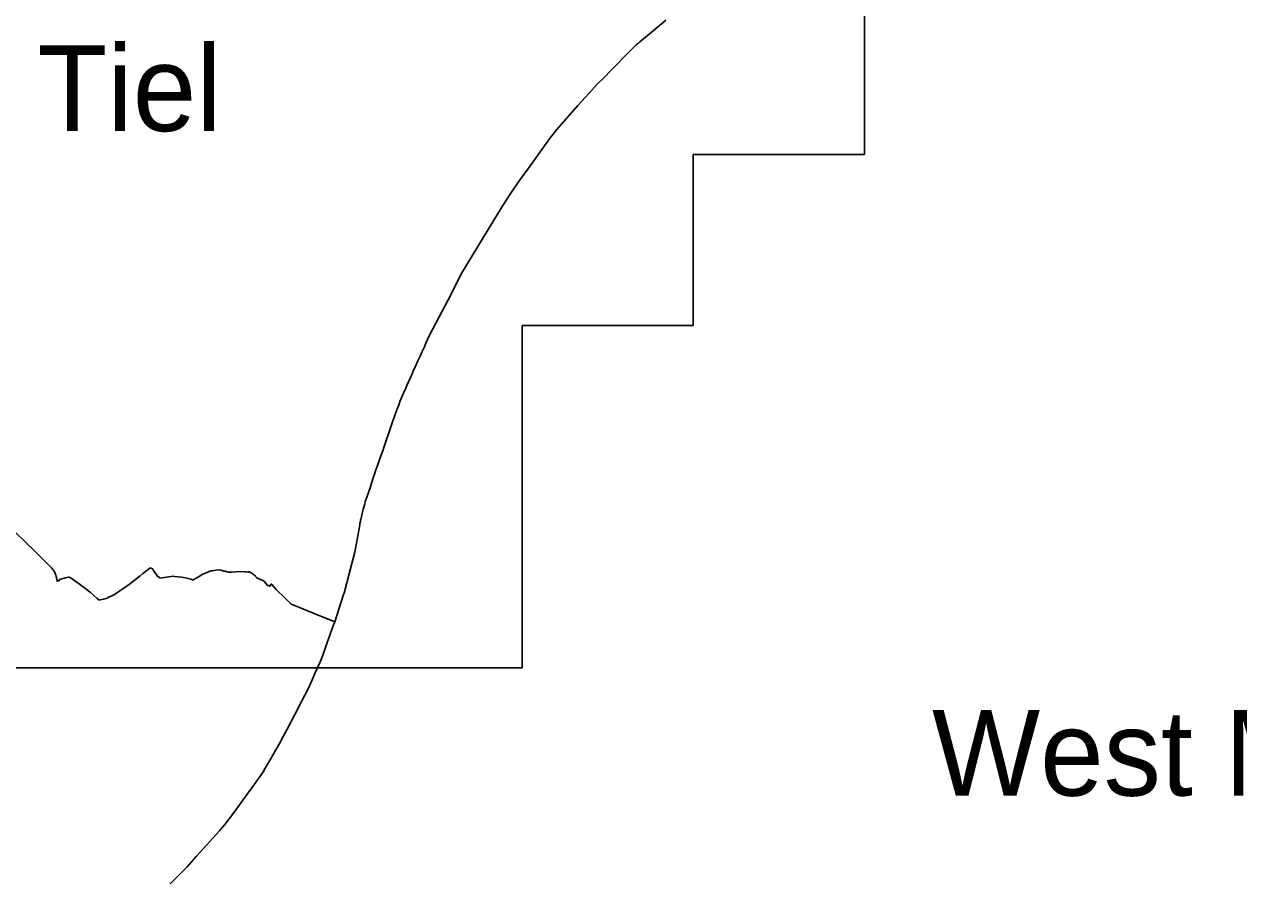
# Model space of a CAD drawing. Extents: x 113371 to 291721, y 393993 to 520143.
# Drawn here: x 155091 to 162187, y 427782 to 432755 of the extents above; entities that cross this region are included whole.
import ezdxf

# ---------------------------------------------------------------- set-up
doc = ezdxf.new("R2010")
doc.units = 0
for name, color, linetype in [('Boudingbox', 7, 'Continuous'), ('Default', 7, 'Continuous'), ('plaatsnamen', 7, 'Continuous'), ('vlieg gebied', 7, 'Continuous')]:
    doc.layers.add(name, color=color, linetype=linetype)

msp = doc.modelspace()

# ---------------------------------------------------------------- linework, layer by layer
at = {"layer": 'Boudingbox'}
for p, q in [((160000, 432995.215), (160000, 431995.215)), ((160000, 431995.215), (159000, 431995.215)), ((159000, 431995.215), (159000, 430995.215)), ((159000, 430995.215), (158000, 430995.215)), ((158000, 430995.215), (158000, 428995.215)), ((158000, 428995.215), (150000, 428995.215))]:
    msp.add_line(p, q, dxfattribs=at)
at = {"layer": 'Default'}
for points in [[(158840.615625, 432779.1125), (158777.135625, 432726.5825), (158720.495625, 432679.8225), (158688.725625, 432653.7425), (158679.835625, 432646.0125), (158669.255625, 432637.2825), (158658.075625, 432627.5925), (158644.595625, 432613.6525), (158602.395625, 432570.3625)], [(158602.395625, 432570.3625), (158644.595625, 432613.6525), (158658.075625, 432627.5925), (158669.255625, 432637.2825), (158679.835625, 432646.0125), (158688.725625, 432653.7425), (158720.495625, 432679.8225), (158777.135625, 432726.5825), (158840.615625, 432779.1125)], [(158602.395625, 432570.3625), (158551.075625, 432518.0425), (158515.545625, 432482.6625), (158480.465625, 432447.2025), (158439.405625, 432406.1125), (158390.795625, 432353.2825), (158344.145625, 432302.1425), (158325.745625, 432281.2925), (158244.325625, 432188.3925), (158240.585625, 432184.1225), (158203.205625, 432141.0825), (158164.965625, 432095.0525), (158114.925625, 432024.0425), (158071.385625, 431963.0225), (158036.605625, 431914.7325), (157989.405625, 431849.3225), (157948.955625, 431792.0025), (157930.655625, 431763.4525), (157887.545625, 431696.9025), (157856.185625, 431646.8425), (157647.905625, 431303.6125), (157566.495625, 431142.2825), (157513.785625, 431042.1125), (157457.465625, 430935.1025), (157438.405625, 430892.8725), (157428.825625, 430871.2225), (157416.765625, 430844.7025), (157404.285625, 430817.3225), (157391.425625, 430789.3325), (157377.655625, 430758.6825), (157364.215625, 430728.8825), (157357.545625, 430712.9125), (157347.615625, 430691.4325), (157336.865625, 430667.1625), (157327.405625, 430646.2725), (157320.235625, 430630.2625), (157308.905625, 430604.8925), (157305.375625, 430596.2825)], [(157305.375625, 430596.2825), (157308.905625, 430604.8925), (157320.235625, 430630.2625), (157327.405625, 430646.2725), (157336.865625, 430667.1625), (157347.615625, 430691.4325), (157357.545625, 430712.9125), (157364.215625, 430728.8825), (157377.655625, 430758.6825), (157391.425625, 430789.3325), (157404.285625, 430817.3225), (157416.765625, 430844.7025), (157428.825625, 430871.2225), (157438.405625, 430892.8725), (157457.465625, 430935.1025), (157513.785625, 431042.1125), (157566.495625, 431142.2825), (157647.905625, 431303.6125), (157856.185625, 431646.8425), (157887.545625, 431696.9025), (157930.655625, 431763.4525), (157948.955625, 431792.0025), (157989.405625, 431849.3225), (158036.605625, 431914.7325), (158071.385625, 431963.0225), (158114.925625, 432024.0425), (158164.965625, 432095.0525), (158203.205625, 432141.0825), (158240.585625, 432184.1225), (158244.325625, 432188.3925), (158325.745625, 432281.2925), (158344.145625, 432302.1425), (158390.795625, 432353.2825), (158439.405625, 432406.1125), (158480.465625, 432447.2025), (158515.545625, 432482.6625), (158551.075625, 432518.0425), (158602.395625, 432570.3625)], [(156784.805625, 429313.8825), (156905.645625, 429265.7325), (156956.895625, 429424.4425), (156959.555625, 429432.2025), (157005.475625, 429604.8225), (157022.755625, 429671.6825), (157051.655625, 429831.9825), (157052.535625, 429841.1825), (157053.465625, 429846.7025), (157055.055625, 429851.8625), (157056.625625, 429859.7625), (157059.225625, 429869.2725), (157061.695625, 429880.2125), (157072.155625, 429922.1725), (157074.095625, 429929.7325), (157080.355625, 429954.0125), (157083.855625, 429965.7025), (157111.675625, 430048.1325), (157128.605625, 430099.8925), (157137.745625, 430128.1425), (157142.255625, 430140.1425), (157152.885625, 430171.8225), (157164.585625, 430205.7225), (157174.715625, 430235.1225), (157185.555625, 430264.5125), (157191.935625, 430283.7325), (157201.525625, 430311.5225), (157205.265625, 430323.3825), (157218.825625, 430363.8925), (157230.305625, 430397.1825), (157236.095625, 430415.4925), (157244.085625, 430439.0025), (157247.575625, 430448.6825), (157268.435625, 430504.0325), (157276.915625, 430526.5625), (157287.845625, 430554.9325), (157293.215625, 430569.8125), (157305.375625, 430596.2825)], [(157305.375625, 430596.2825), (157293.215625, 430569.8125), (157287.845625, 430554.9325), (157276.915625, 430526.5625), (157268.435625, 430504.0325), (157247.575625, 430448.6825), (157244.085625, 430439.0025), (157236.095625, 430415.4925), (157230.305625, 430397.1825), (157218.825625, 430363.8925), (157205.265625, 430323.3825), (157201.525625, 430311.5225), (157191.935625, 430283.7325), (157185.555625, 430264.5125), (157174.715625, 430235.1225), (157164.585625, 430205.7225), (157152.885625, 430171.8225), (157142.255625, 430140.1425), (157137.745625, 430128.1425), (157128.605625, 430099.8925), (157111.675625, 430048.1325), (157083.855625, 429965.7025), (157080.355625, 429954.0125), (157074.095625, 429929.7325), (157072.155625, 429922.1725), (157061.695625, 429880.2125), (157059.225625, 429869.2725), (157056.625625, 429859.7625), (157055.055625, 429851.8625), (157053.465625, 429846.7025), (157052.535625, 429841.1825), (157051.655625, 429831.9825), (157022.755625, 429671.6825), (157005.475625, 429604.8225), (156959.555625, 429432.2025), (156956.895625, 429424.4425), (156905.645625, 429265.7325), (156898.295625, 429246.5025)], [(155357.905625, 429523.9125), (155352.895625, 429525.4725), (155348.495625, 429525.6425), (155332.525625, 429521.3325), (155303.785625, 429513.5325), (155297.835625, 429511.2225), (155295.425625, 429508.6225), (155295.225625, 429505.6225), (155283.335625, 429501.5225), (155281.665625, 429515.3325), (155278.315625, 429529.9025), (155276.185625, 429537.4825), (155274.045625, 429543.0225), (155272.455625, 429547.2225), (155270.085625, 429552.6025), (155267.595625, 429557.4025), (155261.815625, 429566.1325), (155257.955625, 429571.2025), (155250.265625, 429580.5325), (155240.885625, 429590.6125), (155145.715625, 429685.5625), (155106.945625, 429722.6625), (155025.835625, 429800.4525)], [(155025.835625, 429800.4525), (155106.945625, 429722.6625), (155145.715625, 429685.5625), (155240.885625, 429590.6125), (155250.265625, 429580.5325), (155257.955625, 429571.2025), (155261.815625, 429566.1325), (155267.595625, 429557.4025), (155270.085625, 429552.6025), (155272.455625, 429547.2225), (155274.045625, 429543.0225), (155276.185625, 429537.4825), (155278.315625, 429529.9025), (155281.665625, 429515.3325), (155283.335625, 429501.5225), (155295.225625, 429505.6225), (155295.425625, 429508.6225), (155297.835625, 429511.2225), (155303.785625, 429513.5325), (155332.525625, 429521.3325), (155348.495625, 429525.6425), (155352.895625, 429525.4725), (155357.905625, 429523.9125), (155361.525625, 429521.7425), (155365.135625, 429519.3625), (155405.725625, 429491.0625), (155420.395625, 429480.5725), (155461.605625, 429449.0825), (155476.085625, 429437.9925), (155517.735625, 429401.7025), (155528.005625, 429391.3825), (155535.585625, 429392.6325)], [(155989.985625, 429528.0325), (155971.785625, 429529.3025), (155960.175625, 429530.8125), (155949.985625, 429529.7425), (155936.245625, 429527.4725), (155883.655625, 429520.4725), (155880.925625, 429523.8925), (155879.215625, 429526.6425), (155868.575625, 429532.3625), (155864.945625, 429536.5325), (155859.695625, 429544.6925), (155849.995625, 429558.8125), (155840.895625, 429573.7425), (155833.255625, 429579.2925), (155829.255625, 429579.6625), (155824.735625, 429578.9225), (155816.715625, 429572.1525), (155783.695625, 429546.5425), (155765.595625, 429531.0225), (155734.165625, 429507.2125), (155705.525625, 429485.4125), (155667.325625, 429457.5525), (155637.665625, 429437.5425), (155617.555625, 429424.6125), (155610.395625, 429419.7625), (155585.675625, 429407.9825), (155571.525625, 429401.8925), (155552.765625, 429396.5525), (155535.585625, 429392.6325), (155528.005625, 429391.3825), (155517.735625, 429401.7025), (155476.085625, 429437.9925), (155461.605625, 429449.0825), (155420.395625, 429480.5725), (155405.725625, 429491.0625), (155365.135625, 429519.3625), (155361.525625, 429521.7425), (155357.905625, 429523.9125)], [(155535.585625, 429392.6325), (155552.765625, 429396.5525), (155571.525625, 429401.8925), (155585.675625, 429407.9825), (155610.395625, 429419.7625), (155617.555625, 429424.6125), (155637.665625, 429437.5425), (155667.325625, 429457.5525), (155705.525625, 429485.4125), (155734.165625, 429507.2125), (155765.595625, 429531.0225), (155783.695625, 429546.5425), (155816.715625, 429572.1525), (155824.735625, 429578.9225), (155829.255625, 429579.6625), (155833.255625, 429579.2925), (155840.895625, 429573.7425), (155849.995625, 429558.8125), (155859.695625, 429544.6925), (155864.945625, 429536.5325), (155868.575625, 429532.3625), (155879.215625, 429526.6425), (155880.925625, 429523.8925), (155883.655625, 429520.4725), (155936.245625, 429527.4725), (155949.985625, 429529.7425), (155960.175625, 429530.8125), (155971.785625, 429529.3025), (155989.985625, 429528.0325), (156012.605625, 429525.5925), (156040.235625, 429520.5925), (156064.735625, 429514.4525), (156064.965625, 429514.3225), (156070.495625, 429511.4125), (156074.915625, 429508.4425), (156076.625625, 429509.1425), (156077.275625, 429509.4725), (156099.015625, 429521.8125)], [(156413.755625, 429553.2525), (156409.945625, 429554.4225), (156405.535625, 429555.9925), (156402.335625, 429556.1625), (156399.545625, 429555.5425), (156387.735625, 429556.2625), (156381.135625, 429556.8125), (156344.535625, 429557.9525), (156325.745625, 429557.0225), (156302.355625, 429555.4525), (156300.475625, 429555.3425), (156294.165625, 429554.9925), (156283.765625, 429554.7225), (156274.345625, 429557.0525), (156271.465625, 429557.8925), (156264.325625, 429559.9825), (156257.515625, 429561.5325), (156253.915625, 429562.1025), (156239.085625, 429566.3925), (156225.075625, 429568.0925), (156198.225625, 429564.0025), (156187.925625, 429562.4325), (156183.925625, 429561.8025), (156165.565625, 429556.2325), (156163.675625, 429555.5825), (156150.215625, 429549.9725), (156135.265625, 429543.2625), (156119.325625, 429534.1525), (156099.015625, 429521.8125), (156077.275625, 429509.4725), (156076.625625, 429509.1425), (156074.915625, 429508.4425), (156070.495625, 429511.4125), (156064.965625, 429514.3225), (156064.735625, 429514.4525), (156040.235625, 429520.5925), (156012.605625, 429525.5925), (155989.985625, 429528.0325)], [(156099.015625, 429521.8125), (156119.325625, 429534.1525), (156135.265625, 429543.2625), (156150.215625, 429549.9725), (156163.675625, 429555.5825), (156165.565625, 429556.2325), (156183.925625, 429561.8025), (156187.925625, 429562.4325), (156198.225625, 429564.0025), (156225.075625, 429568.0925), (156239.085625, 429566.3925), (156253.915625, 429562.1025), (156257.515625, 429561.5325), (156264.325625, 429559.9825), (156271.465625, 429557.8925), (156274.345625, 429557.0525), (156283.765625, 429554.7225), (156294.165625, 429554.9925), (156300.475625, 429555.3425), (156302.355625, 429555.4525), (156325.745625, 429557.0225), (156344.535625, 429557.9525), (156381.135625, 429556.8125), (156387.735625, 429556.2625), (156399.545625, 429555.5425), (156402.335625, 429556.1625), (156405.535625, 429555.9925), (156409.945625, 429554.4225), (156413.755625, 429553.2525), (156418.575625, 429550.6825), (156425.665625, 429545.3425), (156442.495625, 429532.6625), (156441.205625, 429530.9625), (156450.765625, 429521.7225), (156453.935625, 429520.2725), (156489.315625, 429503.9525), (156492.115625, 429502.5825), (156498.455625, 429494.4325)], [(156486.655625, 428389.2225), (156499.545625, 428410.1825), (156548.865625, 428496.4125), (156552.915625, 428503.5025), (156581.955625, 428553.4125), (156603.975625, 428594.4125), (156627.165625, 428638.6625), (156671.645625, 428724.2225), (156710.285625, 428798.5425), (156749.425625, 428873.5425), (156775.205625, 428930.8825), (156789.265625, 428962.3325), (156822.225625, 429035.8425), (156835.105625, 429069.7025), (156859.655625, 429137.7725), (156898.295625, 429246.5025), (156905.645625, 429265.7325), (156784.805625, 429313.8825), (156699.105625, 429347.9325), (156650.785625, 429367.5325), (156615.955625, 429402.3125), (156562.045625, 429454.4525), (156536.955625, 429483.2425), (156534.675625, 429485.8825), (156527.815625, 429473.1825), (156520.725625, 429477.4725), (156512.015625, 429476.7925), (156502.435625, 429488.9325), (156498.455625, 429494.4325), (156492.115625, 429502.5825), (156489.315625, 429503.9525), (156453.935625, 429520.2725), (156450.765625, 429521.7225), (156441.205625, 429530.9625), (156442.495625, 429532.6625), (156425.665625, 429545.3425), (156418.575625, 429550.6825), (156413.755625, 429553.2525)], [(156498.455625, 429494.4325), (156502.435625, 429488.9325), (156512.015625, 429476.7925), (156520.725625, 429477.4725), (156527.815625, 429473.1825), (156534.675625, 429485.8825), (156536.955625, 429483.2425), (156562.045625, 429454.4525), (156615.955625, 429402.3125), (156650.785625, 429367.5325), (156699.105625, 429347.9325), (156784.805625, 429313.8825)], [(156898.295625, 429246.5025), (156859.655625, 429137.7725), (156835.105625, 429069.7025), (156822.225625, 429035.8425), (156789.265625, 428962.3325), (156775.205625, 428930.8825), (156749.425625, 428873.5425), (156710.285625, 428798.5425), (156671.645625, 428724.2225), (156627.165625, 428638.6625), (156603.975625, 428594.4125), (156581.955625, 428553.4125), (156552.915625, 428503.5025), (156548.865625, 428496.4125), (156499.545625, 428410.1825), (156486.655625, 428389.2225), (156469.265625, 428364.0425), (156436.515625, 428317.2625), (156368.125625, 428222.8725), (156312.785625, 428147.8825), (156262.605625, 428081.2625), (156239.145625, 428052.8025), (156231.245625, 428044.3625), (156098.255625, 427895.4925), (156042.365625, 427833.5825), (155931.275625, 427722.2525)], [(155931.275625, 427722.2525), (156042.365625, 427833.5825), (156098.255625, 427895.4925), (156231.245625, 428044.3625), (156239.145625, 428052.8025), (156262.605625, 428081.2625), (156312.785625, 428147.8825), (156368.125625, 428222.8725), (156436.515625, 428317.2625), (156469.265625, 428364.0425), (156486.655625, 428389.2225)]]:
    msp.add_lwpolyline(points, dxfattribs=at)
at = {"layer": 'vlieg gebied'}
for p, q in [((160000, 432995.215), (160000, 431995.215)), ((160000, 431995.215), (159000, 431995.215)), ((159000, 431995.215), (159000, 430995.215)), ((159000, 430995.215), (158000, 430995.215)), ((158000, 430995.215), (158000, 428995.215)), ((158000, 428995.215), (150000, 428995.215))]:
    msp.add_line(p, q, dxfattribs=at)

# ---------------------------------------------------------------- texts
at = {"layer": 'plaatsnamen'}
for s, p in [('Tiel', (155167.662927, 432131.653089)), ('West Maas en Waal', (160395.115567, 428249.384604))]:
    msp.add_text(s, height=500, dxfattribs=at).set_placement(p)

doc.saveas('drawing.dxf')
